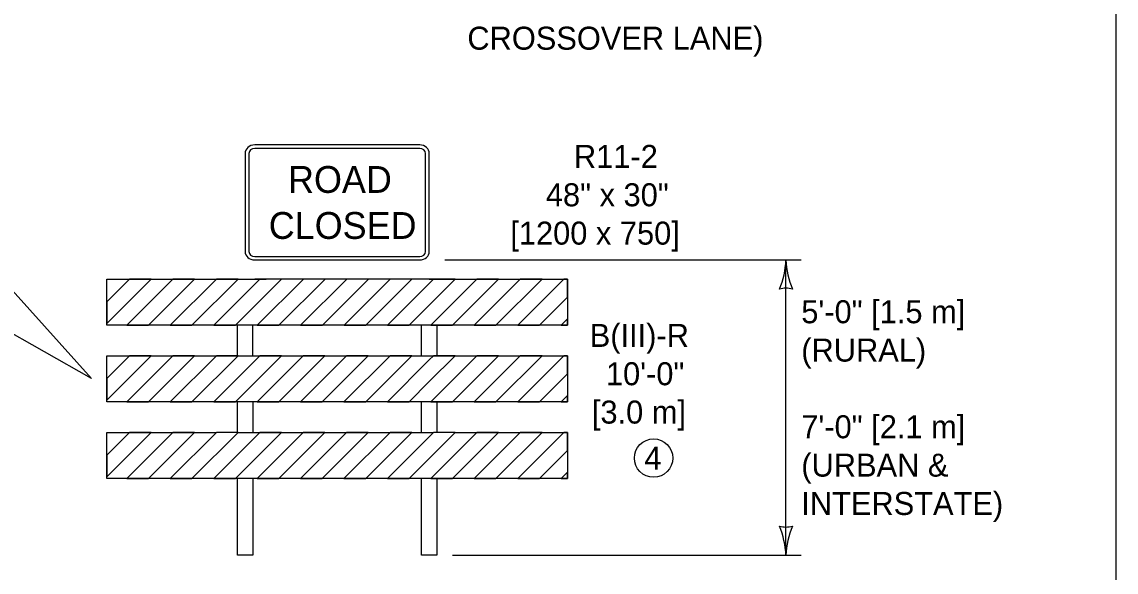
# Model space of a CAD drawing. Extents: x 49991.4 to 50021, y 49987.6 to 50011.4.
# Drawn here: x 50005.764 to 50008.615, y 50004.324 to 50005.759 of the extents above; entities that cross this region are included whole.
import ezdxf

# ---------------------------------------------------------------- set-up
doc = ezdxf.new("R2010")
doc.units = 0
for name, color, linetype in [('Level 1', 7, 'Continuous'), ('Level 2', 7, 'Continuous'), ('Level 3', 7, 'Continuous')]:
    doc.layers.add(name, color=color, linetype=linetype)

msp = doc.modelspace()

# ---------------------------------------------------------------- linework, layer by layer
at = {"layer": 'Level 1'}
for p, q in [((50006.8003, 50005.4381), (50006.3703, 50005.4381)), ((50006.8003, 50005.4291), (50006.3703, 50005.4291)), ((50006.3453, 50005.4156), (50006.3453, 50005.1606)), ((50006.3553, 50005.4156), (50006.3553, 50005.1606)), ((50006.8153, 50005.1606), (50006.8153, 50005.4156)), ((50006.8253, 50005.1606), (50006.8253, 50005.4156)), ((50006.3703, 50005.1471), (50006.8003, 50005.1471)), ((50006.3703, 50005.1381), (50006.8003, 50005.1381)), ((50005.9853, 50004.9726), (50006.1008, 50005.0881)), ((50005.9853, 50005.0292), (50006.0442, 50005.0881)), ((50006.0442, 50005.0881), (50005.9853, 50005.0292)), ((50005.9853, 50004.9726), (50006.1008, 50005.0881)), ((50006.0374, 50004.9681), (50006.1574, 50005.0881)), ((50006.1574, 50005.0881), (50006.0374, 50004.9681)), ((50006.0939, 50004.9681), (50006.2139, 50005.0881)), ((50006.0939, 50004.9681), (50006.2139, 50005.0881)), ((50006.1505, 50004.9681), (50006.2705, 50005.0881)), ((50006.2705, 50005.0881), (50006.1505, 50004.9681)), ((50006.207, 50004.9681), (50006.327, 50005.0881)), ((50006.207, 50004.9681), (50006.327, 50005.0881)), ((50006.2636, 50004.9681), (50006.3836, 50005.0881)), ((50006.3202, 50004.9681), (50006.4402, 50005.0881)), ((50006.3453, 50005.0881), (50006.4002, 50005.0881)), ((50006.8003, 50005.0881), (50006.3703, 50005.0881)), ((50006.3771, 50004.9681), (50006.4971, 50005.0881)), ((50006.4336, 50004.9681), (50006.5536, 50005.0881)), ((50006.4901, 50004.9681), (50006.6101, 50005.0881)), ((50006.5466, 50004.9681), (50006.6666, 50005.0881)), ((50006.6031, 50004.9681), (50006.7231, 50005.0881)), ((50006.6596, 50004.9681), (50006.7796, 50005.0881)), ((50006.7161, 50004.9681), (50006.8361, 50005.0881)), ((50006.8361, 50005.0881), (50006.7661, 50005.0881)), ((50006.7726, 50004.9681), (50006.8926, 50005.0881)), ((50006.8292, 50004.9681), (50006.9492, 50005.0881)), ((50006.9492, 50005.0881), (50006.8292, 50004.9681)), ((50006.8858, 50004.9681), (50007.0058, 50005.0881)), ((50006.8858, 50004.9681), (50007.0058, 50005.0881)), ((50006.9423, 50004.9681), (50007.0623, 50005.0881)), ((50007.0623, 50005.0881), (50006.9423, 50004.9681)), ((50006.9989, 50004.9681), (50007.1189, 50005.0881)), ((50006.9989, 50004.9681), (50007.1189, 50005.0881)), ((50007.0555, 50004.9681), (50007.1755, 50005.0881)), ((50007.1755, 50005.0881), (50007.0555, 50004.9681)), ((50007.112, 50004.9681), (50007.1853, 50005.0414)), ((50007.112, 50004.9681), (50007.1853, 50005.0414)), ((50007.1686, 50004.9681), (50007.1853, 50004.9848)), ((50007.1853, 50004.9848), (50007.1686, 50004.9681)), ((50006.3653, 50004.8882), (50006.3653, 50004.9681)), ((50006.8053, 50004.8882), (50006.8053, 50004.9681)), ((50005.9853, 50004.7727), (50006.1008, 50004.8882)), ((50005.9853, 50004.8292), (50006.0442, 50004.8882)), ((50006.0442, 50004.8882), (50005.9853, 50004.8292)), ((50005.9853, 50004.7727), (50006.1008, 50004.8882)), ((50006.0374, 50004.7682), (50006.1574, 50004.8882)), ((50006.1574, 50004.8882), (50006.0374, 50004.7682)), ((50006.0939, 50004.7682), (50006.2139, 50004.8882)), ((50006.0939, 50004.7682), (50006.2139, 50004.8882)), ((50006.1505, 50004.7682), (50006.2705, 50004.8882)), ((50006.2705, 50004.8882), (50006.1505, 50004.7682)), ((50006.207, 50004.7682), (50006.327, 50004.8882)), ((50006.207, 50004.7682), (50006.327, 50004.8882)), ((50006.2636, 50004.7682), (50006.3836, 50004.8882)), ((50006.3202, 50004.7682), (50006.4402, 50004.8882)), ((50006.3767, 50004.7682), (50006.4967, 50004.8882)), ((50006.4333, 50004.7682), (50006.5533, 50004.8882)), ((50006.4898, 50004.7682), (50006.6098, 50004.8882)), ((50006.5464, 50004.7682), (50006.6664, 50004.8882)), ((50006.603, 50004.7682), (50006.723, 50004.8882)), ((50006.6595, 50004.7682), (50006.7795, 50004.8882)), ((50006.8253, 50004.8209), (50006.8926, 50004.8882)), ((50006.8253, 50004.8774), (50006.8361, 50004.8882)), ((50006.8292, 50004.7682), (50006.9492, 50004.8882)), ((50006.9492, 50004.8882), (50006.8292, 50004.7682)), ((50006.8858, 50004.7682), (50007.0058, 50004.8882)), ((50006.8858, 50004.7682), (50007.0058, 50004.8882)), ((50006.9423, 50004.7682), (50007.0623, 50004.8882)), ((50007.0623, 50004.8882), (50006.9423, 50004.7682)), ((50006.9989, 50004.7682), (50007.1189, 50004.8882)), ((50006.9989, 50004.7682), (50007.1189, 50004.8882)), ((50007.0555, 50004.7682), (50007.1755, 50004.8882)), ((50007.1755, 50004.8882), (50007.0555, 50004.7682)), ((50006.7161, 50004.7682), (50006.8253, 50004.8774)), ((50007.112, 50004.7682), (50007.1853, 50004.8414)), ((50007.112, 50004.7682), (50007.1853, 50004.8414)), ((50006.7726, 50004.7682), (50006.8253, 50004.8209)), ((50007.1686, 50004.7682), (50007.1853, 50004.7849)), ((50007.1853, 50004.7849), (50007.1686, 50004.7682)), ((50005.9853, 50004.5727), (50006.1008, 50004.6883)), ((50005.9853, 50004.6293), (50006.0442, 50004.6883)), ((50006.0442, 50004.6883), (50005.9853, 50004.6293)), ((50005.9853, 50004.5727), (50006.1008, 50004.6883)), ((50006.0374, 50004.5683), (50006.1574, 50004.6883)), ((50006.1574, 50004.6883), (50006.0374, 50004.5683)), ((50006.0939, 50004.5683), (50006.2139, 50004.6883)), ((50006.0939, 50004.5683), (50006.2139, 50004.6883)), ((50006.1505, 50004.5683), (50006.2705, 50004.6883)), ((50006.2705, 50004.6883), (50006.1505, 50004.5683)), ((50006.207, 50004.5683), (50006.327, 50004.6883)), ((50006.207, 50004.5683), (50006.327, 50004.6883)), ((50006.2636, 50004.5683), (50006.3836, 50004.6883)), ((50006.3836, 50004.6883), (50006.2636, 50004.5683)), ((50006.3202, 50004.5683), (50006.4402, 50004.6883)), ((50006.3202, 50004.5683), (50006.4402, 50004.6883)), ((50006.3767, 50004.5683), (50006.4967, 50004.6883)), ((50006.4967, 50004.6883), (50006.3767, 50004.5683)), ((50006.4333, 50004.5683), (50006.5533, 50004.6883)), ((50006.4333, 50004.5683), (50006.5533, 50004.6883)), ((50006.4898, 50004.5683), (50006.6098, 50004.6883)), ((50006.6098, 50004.6883), (50006.4898, 50004.5683)), ((50006.5464, 50004.5683), (50006.6664, 50004.6883)), ((50006.5464, 50004.5683), (50006.6664, 50004.6883)), ((50006.603, 50004.5683), (50006.723, 50004.6883)), ((50006.723, 50004.6883), (50006.603, 50004.5683)), ((50006.6595, 50004.5683), (50006.7795, 50004.6883)), ((50006.6595, 50004.5683), (50006.7795, 50004.6883)), ((50006.7161, 50004.5683), (50006.8361, 50004.6883)), ((50006.8361, 50004.6883), (50006.7161, 50004.5683)), ((50006.7726, 50004.5683), (50006.8926, 50004.6883)), ((50006.7726, 50004.5683), (50006.8926, 50004.6883)), ((50006.8292, 50004.5683), (50006.9492, 50004.6883)), ((50006.9492, 50004.6883), (50006.8292, 50004.5683)), ((50006.8858, 50004.5683), (50007.0058, 50004.6883)), ((50006.8858, 50004.5683), (50007.0058, 50004.6883)), ((50006.9423, 50004.5683), (50007.0623, 50004.6883)), ((50007.0623, 50004.6883), (50006.9423, 50004.5683)), ((50006.9989, 50004.5683), (50007.1189, 50004.6883)), ((50006.9989, 50004.5683), (50007.1189, 50004.6883)), ((50007.0555, 50004.5683), (50007.1755, 50004.6883)), ((50007.1755, 50004.6883), (50007.0555, 50004.5683)), ((50007.112, 50004.5683), (50007.1853, 50004.6415)), ((50007.112, 50004.5683), (50007.1853, 50004.6415)), ((50007.1686, 50004.5683), (50007.1853, 50004.585)), ((50007.1853, 50004.585), (50007.1686, 50004.5683))]:
    msp.add_line(p, q, dxfattribs=at)
msp.add_lwpolyline([(50008.6146, 50011.2628), (50000.3356, 50011.2628), (50000.3356, 50000.0624), (50008.6146, 50000.0624)], close=True, dxfattribs=at)
for points in [[(50006.8253, 50004.9681), (50005.9853, 50004.9681), (50005.9853, 50005.0881), (50006.3453, 50005.0881)], [(50006.1008, 50005.0881), (50006.0442, 50005.0881)], [(50006.2139, 50005.0881), (50006.1574, 50005.0881)], [(50006.4402, 50005.0881), (50006.4002, 50005.0881), (50006.3836, 50005.0881), (50006.2636, 50004.9681), (50006.3202, 50004.9681), (50006.4402, 50005.0881)], [(50006.327, 50005.0881), (50006.2705, 50005.0881)], [(50006.5536, 50005.0881), (50006.4971, 50005.0881), (50006.3771, 50004.9681), (50006.4336, 50004.9681), (50006.5536, 50005.0881)], [(50006.6666, 50005.0881), (50006.6101, 50005.0881), (50006.4901, 50004.9681), (50006.5466, 50004.9681), (50006.6666, 50005.0881)], [(50006.7796, 50005.0881), (50006.7661, 50005.0881), (50006.7231, 50005.0881), (50006.6031, 50004.9681), (50006.6596, 50004.9681), (50006.7796, 50005.0881)], [(50006.7161, 50004.9681), (50006.7726, 50004.9681), (50006.8926, 50005.0881), (50006.8361, 50005.0881), (50006.7161, 50004.9681)], [(50006.8253, 50005.0881), (50007.1853, 50005.0881), (50007.1853, 50004.9681), (50006.8253, 50004.9681)], [(50007.0058, 50005.0881), (50006.9492, 50005.0881)], [(50007.1189, 50005.0881), (50007.0623, 50005.0881)], [(50007.1853, 50005.0414), (50007.1853, 50005.0881), (50007.1755, 50005.0881)], [(50005.9853, 50005.0292), (50005.9853, 50004.9726)], [(50007.1686, 50004.9681), (50007.1853, 50004.9681), (50007.1853, 50004.9848)], [(50006.0374, 50004.9681), (50006.0939, 50004.9681)], [(50006.1505, 50004.9681), (50006.207, 50004.9681)], [(50006.3253, 50004.8881), (50006.3253, 50004.9681)], [(50006.8292, 50004.9681), (50006.8858, 50004.9681)], [(50006.8453, 50004.9681), (50006.8453, 50004.8882)], [(50006.9423, 50004.9681), (50006.9989, 50004.9681)], [(50007.0555, 50004.9681), (50007.112, 50004.9681)], [(50006.8253, 50004.8882), (50007.1853, 50004.8882), (50007.1853, 50004.7682), (50005.9853, 50004.7682), (50005.9853, 50004.8882), (50006.8253, 50004.8882)], [(50006.1008, 50004.8882), (50006.0442, 50004.8882)], [(50006.2139, 50004.8882), (50006.1574, 50004.8882)], [(50006.4402, 50004.8882), (50006.3836, 50004.8882), (50006.2636, 50004.7682), (50006.3202, 50004.7682), (50006.4402, 50004.8882)], [(50006.327, 50004.8882), (50006.2705, 50004.8882)], [(50006.5533, 50004.8882), (50006.4967, 50004.8882), (50006.3767, 50004.7682), (50006.4333, 50004.7682), (50006.5533, 50004.8882)], [(50006.6664, 50004.8882), (50006.6098, 50004.8882), (50006.4898, 50004.7682), (50006.5464, 50004.7682), (50006.6664, 50004.8882)], [(50006.7795, 50004.8882), (50006.723, 50004.8882), (50006.603, 50004.7682), (50006.6595, 50004.7682), (50006.7795, 50004.8882)], [(50006.7161, 50004.7682), (50006.7726, 50004.7682), (50006.8253, 50004.8209), (50006.8926, 50004.8882), (50006.8453, 50004.8882), (50006.8361, 50004.8882), (50006.8253, 50004.8774), (50006.7161, 50004.7682)], [(50007.0058, 50004.8882), (50006.9492, 50004.8882)], [(50007.1189, 50004.8882), (50007.0623, 50004.8882)], [(50007.1853, 50004.8414), (50007.1853, 50004.8882), (50007.1755, 50004.8882)], [(50005.9853, 50004.8292), (50005.9853, 50004.7727)], [(50007.1686, 50004.7682), (50007.1853, 50004.7682), (50007.1853, 50004.7849)], [(50006.0374, 50004.7682), (50006.0939, 50004.7682)], [(50006.1505, 50004.7682), (50006.207, 50004.7682)], [(50006.3253, 50004.6883), (50006.3253, 50004.7682)], [(50006.3653, 50004.7682), (50006.3653, 50004.6883)], [(50006.8053, 50004.6883), (50006.8053, 50004.7682)], [(50006.8292, 50004.7682), (50006.8858, 50004.7682)], [(50006.8453, 50004.7682), (50006.8453, 50004.6883)], [(50006.9423, 50004.7682), (50006.9989, 50004.7682)], [(50007.0555, 50004.7682), (50007.112, 50004.7682)], [(50006.8926, 50004.6883), (50007.1853, 50004.6883), (50007.1853, 50004.5683), (50005.9853, 50004.5683), (50005.9853, 50004.6883), (50006.2705, 50004.6883)], [(50006.1008, 50004.6883), (50006.0442, 50004.6883)], [(50006.2139, 50004.6883), (50006.1574, 50004.6883)], [(50006.327, 50004.6883), (50006.2705, 50004.6883)], [(50006.327, 50004.6883), (50006.8361, 50004.6883)], [(50006.4402, 50004.6883), (50006.3836, 50004.6883)], [(50006.5533, 50004.6883), (50006.4967, 50004.6883)], [(50006.6664, 50004.6883), (50006.6098, 50004.6883)], [(50006.7795, 50004.6883), (50006.723, 50004.6883)], [(50006.8926, 50004.6883), (50006.8361, 50004.6883)], [(50007.0058, 50004.6883), (50006.9492, 50004.6883)], [(50007.1189, 50004.6883), (50007.0623, 50004.6883)], [(50007.1853, 50004.6415), (50007.1853, 50004.6883), (50007.1755, 50004.6883)], [(50005.9853, 50004.6293), (50005.9853, 50004.5727)], [(50007.1686, 50004.5683), (50007.1853, 50004.5683), (50007.1853, 50004.585)], [(50006.0374, 50004.5683), (50006.0939, 50004.5683)], [(50006.1505, 50004.5683), (50006.207, 50004.5683)], [(50006.2636, 50004.5683), (50006.3202, 50004.5683)], [(50006.3653, 50004.5681), (50006.3653, 50004.3681), (50006.3253, 50004.3681), (50006.3253, 50004.5681)], [(50006.3767, 50004.5683), (50006.4333, 50004.5683)], [(50006.4898, 50004.5683), (50006.5464, 50004.5683)], [(50006.603, 50004.5683), (50006.6595, 50004.5683)], [(50006.7161, 50004.5683), (50006.7726, 50004.5683)], [(50006.8453, 50004.5681), (50006.8453, 50004.3681), (50006.8053, 50004.3681), (50006.8053, 50004.5681)], [(50006.8292, 50004.5683), (50006.8858, 50004.5683)], [(50006.9423, 50004.5683), (50006.9989, 50004.5683)], [(50007.0555, 50004.5683), (50007.112, 50004.5683)]]:
    msp.add_lwpolyline(points, dxfattribs=at)
for centre, major_axis, start_param, end_param in [((50006.3703, 50005.4156), (-0.025, 0), 4.712389, 6.283185), ((50006.3703, 50005.4156), (-0.015, 0), 4.712389, 6.283185), ((50006.8003, 50005.4156), (0.025, 0), 0, 1.570796), ((50006.8003, 50005.4156), (0.015, 0), 0, 1.570796), ((50006.3703, 50005.1606), (-0.025, 0), 0, 1.570796), ((50006.3703, 50005.1606), (-0.015, 0), 0, 1.570796), ((50006.8003, 50005.1606), (0.025, 0), 4.712389, 6.283185), ((50006.8003, 50005.1606), (0.015, 0), 4.712389, 6.283185)]:
    msp.add_ellipse(centre, major_axis=major_axis, ratio=0.9, start_param=start_param, end_param=end_param, dxfattribs=at)
at = {"layer": 'Level 2'}
msp.add_circle((50007.4095, 50004.6214), 0.05, dxfattribs=at)
at = {"layer": 'Level 3'}
for p, q in [((50005.9453, 50004.8292), (50004.9734, 50005.9081)), ((50005.9453, 50004.8292), (50005.2517, 50005.2208)), ((50006.8653, 50005.1381), (50007.7944, 50005.1381)), ((50007.7544, 50004.3681), (50007.7544, 50005.1381)), ((50006.8853, 50004.3681), (50007.7944, 50004.3681))]:
    msp.add_line(p, q, dxfattribs=at)
for centre, radius, start, end in [((50007.5323, 50005.1473), 0.2223, 337.456, 357.6395), ((50007.9871, 50005.1496), 0.233, 182.8273, 202.0772), ((50007.7544, 50005.0099), 0.0548, 72.1388, 107.8612), ((50007.7544, 50004.4964), 0.0548, 252.1388, 287.8612), ((50007.5217, 50004.3567), 0.233, 2.8273, 22.0772), ((50007.9765, 50004.359), 0.2223, 157.456, 177.6395)]:
    msp.add_arc(centre, radius, start, end, dxfattribs=at)

# ---------------------------------------------------------------- texts
at = {"layer": 'Level 1'}
for s, p in [('ROAD', (50006.4572, 50005.3131)), ('CLOSED', (50006.407, 50005.1931))]:
    msp.add_text(s, height=0.07, dxfattribs=at).set_placement(p)
at = {"layer": 'Level 2'}
for s, p in [('CROSSOVER LANE)', (50006.9244, 50005.6865)), ('R11-2', (50007.2021, 50005.3781)), ('48" x 30"', (50007.1289, 50005.2781)), ('[1200 x 750]', (50007.0363, 50005.1781)), ('5\'-0" [1.5 m]', (50007.7944, 50004.9731)), ('B(III)-R', (50007.2432, 50004.9114)), ('(RURAL)', (50007.7944, 50004.8731)), (' 10\'-0"', (50007.2631, 50004.8114)), ('[3.0 m]', (50007.2488, 50004.7114)), ('7\'-0" [2.1 m]', (50007.7944, 50004.6731)), ('4', (50007.3855, 50004.5916)), ('(URBAN &', (50007.7944, 50004.5731)), ('INTERSTATE)', (50007.7944, 50004.4731))]:
    msp.add_text(s, height=0.06, dxfattribs=at).set_placement(p)

doc.saveas('drawing.dxf')
